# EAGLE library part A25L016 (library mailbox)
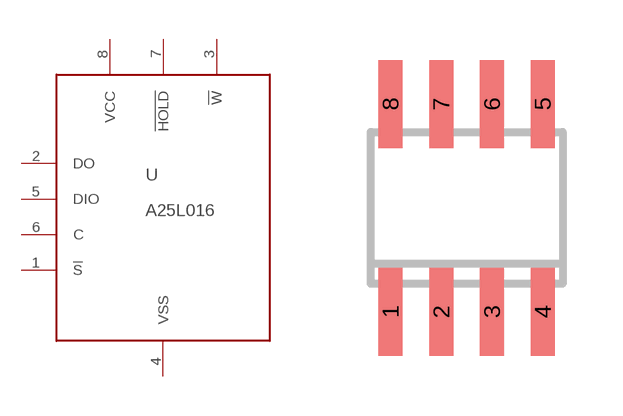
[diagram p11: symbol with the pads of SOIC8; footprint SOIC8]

Designator prefix -

## A25L016  [SOIC8]
1  !S
2  DO
3  !W
4  VSS
5  DIO
6  C
7  !HOLD
8  VCC

## Footprint SOIC8 (pad centres in mm)
Small Outline IC
smd 0.6 x 2.2: 1 -1.905,-2.6; 2 -0.635,-2.6; 3 0.635,-2.6; 4 1.905,-2.6; 5 1.905,2.6; 6 0.635,2.6; 7 -0.635,2.6; 8 -1.905,2.6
